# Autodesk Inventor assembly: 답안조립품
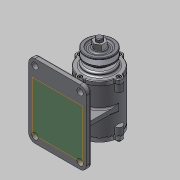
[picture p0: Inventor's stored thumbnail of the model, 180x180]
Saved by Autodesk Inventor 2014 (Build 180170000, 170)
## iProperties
Created: 2015-12
Part Number: 답안조립품
Document SubType Name: Assembly
Designer: user
Mass: 1367.71 g
Surface Area: 1526.01 cm^2
Volume: 629.662 cm^3
Density: 2.17213 g/cm^3
Author: user
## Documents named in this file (10)
- C:\Users\user\Desktop\451208V1017\답안조립품.iam
- C:\Users\user\Desktop\451208V1017\V-벨트풀리.ipt
- C:\Users\user\Desktop\451208V1017\너트 M12x1.25.ipt
- C:\Users\user\Desktop\451208V1017\베어링 6204.ipt
- C:\Users\user\Desktop\451208V1017\본체.ipt
- C:\Users\user\Desktop\451208V1017\볼트 M4 x 12.ipt
- C:\Users\user\Desktop\451208V1017\축.ipt
- C:\Users\user\Desktop\451208V1017\커버.ipt
- C:\Users\user\Desktop\451208V1017\커버2.ipt
- C:\Users\user\Desktop\451208V1017\키(4 x 4 x 12).ipt
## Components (5 placed, 4 different names)
1. V-벨트풀리:1 — Angle:1, Insert:6, Insert:8
2. KS B 1012 클래스 1 일반 - 미터 M12x1.25:1 — Insert:8
3. KS B 2023 6204 - 20 x 47 x 14:1 — Insert:3, Insert:7
4. KS B 1311 (I) 4 x 4 x 12:1 — Insert:5, Mate:3, Angle:1
5. KS B 2023 6204 - 20 x 47 x 14:2 — Insert:4
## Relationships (8: Insert 6, Mate 1, Angle 1)
- Insert:3: KS B 2023 6204 - 20 x 47 x 14:1
- Insert:4: KS B 2023 6204 - 20 x 47 x 14:2
- Insert:5: KS B 1311 (I) 4 x 4 x 12:1
- Mate:3: KS B 1311 (I) 4 x 4 x 12:1
- Angle:1: V-벨트풀리:1 ↔ KS B 1311 (I) 4 x 4 x 12:1
- Insert:6: V-벨트풀리:1
- Insert:7: KS B 2023 6204 - 20 x 47 x 14:1
- Insert:8: V-벨트풀리:1 ↔ KS B 1012 클래스 1 일반 - 미터 M12x1.25:1
